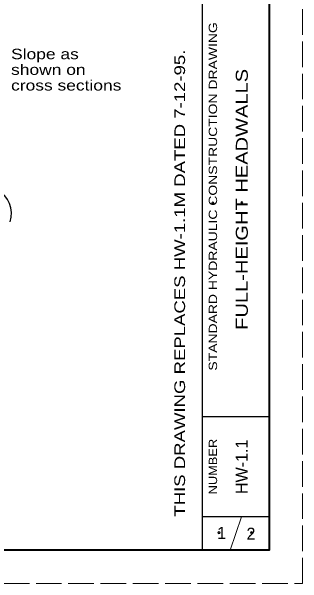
# Model space of a CAD drawing. Extents: x 1083.1 to 1117.1, y 697.4 to 743.4.
# Drawn here: x 1112.77 to 1117.13, y 721.35 to 729.93 of the extents above; entities that cross this region are included whole.
import ezdxf
from ezdxf.enums import TextEntityAlignment as Align

# ---------------------------------------------------------------- set-up
doc = ezdxf.new("R2010")
doc.units = 0
doc.header["$LTSCALE"] = 0.064
doc.header["$PDMODE"] = 32
doc.header["$PDSIZE"] = 0.032
doc.linetypes.add('LONG_DASHED', pattern=[7.5, 6, -1.5])
doc.layers.add('1', color=7, linetype='Continuous', lineweight=13)

msp = doc.modelspace()

# ---------------------------------------------------------------- linework, layer by layer
at = {"layer": '1', "lineweight": 25}
for p, q in [((1115.62642, 721.85408), (1115.62642, 742.85408)), ((1116.62642, 723.85408), (1115.62642, 723.85408)), ((1116.62642, 722.35408), (1115.62642, 722.35408))]:
    msp.add_line(p, q, dxfattribs=at)
at = {"layer": '1'}
msp.add_line((1116.04308, 721.85408), (1116.20975, 722.35408), dxfattribs=at)
at = {"layer": '1', "linetype": 'LONG_DASHED'}
msp.add_lwpolyline([(1083.12642, 721.35408), (1117.12642, 721.35408), (1117.12642, 743.35408), (1083.12642, 743.35408)], close=True, dxfattribs=at)
at = {"layer": '1', "lineweight": 25}
msp.add_lwpolyline([(1085.12642, 742.85408), (1116.62642, 742.85408), (1116.62642, 721.85408), (1085.12642, 721.85408)], close=True, dxfattribs=at)
at = {"layer": '1', "lineweight": 40}
msp.add_lwpolyline([(1085.12642, 742.85408), (1116.62642, 742.85408), (1116.62642, 721.85408), (1085.12642, 721.85408)], close=True, dxfattribs=at)
msp.add_lwpolyline([(1085.12642, 742.85408), (1116.62642, 742.85408), (1116.62642, 721.85408), (1085.12642, 721.85408)], close=True, dxfattribs=at)
at = {"layer": '1', "lineweight": 25}
msp.add_ellipse((1112.36624, 726.90056), major_axis=(0.40134, 0), ratio=0.999895, start_param=5.9747024, end_param=7.3677783, dxfattribs=at)
at = {"layer": '1'}
for p in [(1115.78383, 727.06008), (1116.21667, 727.06742), (1115.8745, 722.11783), (1116.36292, 722.11683)]:
    msp.add_point(p, dxfattribs=at)

# ---------------------------------------------------------------- texts
for s, height, width, p in [('STANDARD HYDRAULIC CONSTRUCTION DRAWING', 0.125, 1.25, (1115.84633, 727.15812)), ('THIS DRAWING REPLACES HW-1.1M DATED 7-12-95.', 0.16, 1.3, (1115.36683, 725.85787)), ('FULL-HEIGHT HEADWALLS', 0.18, 1.25, (1116.30683, 727.11425)), ('NUMBER', 0.125, 1.15, (1115.84642, 723.10817))]:
    msp.add_text(s, height=height, rotation=90, dxfattribs=dict(at, width=width)).set_placement(p, align=Align.CENTER)
at = {"layer": '1', "width": 1.25}
for s, p in [('Slope as', (1112.761, 729.21533)), ('shown on', (1112.761, 728.98067)), ('cross sections', (1112.761, 728.746))]:
    msp.add_text(s, height=0.156, dxfattribs=at).set_placement(p)
at = {"layer": '1'}
msp.add_text('HW-1.1', height=0.18, rotation=90, dxfattribs=at).set_placement((1116.3055, 723.10442), align=Align.CENTER)
for s, p in [('1', (1115.91427, 722.02417)), ('2', (1116.35371, 722.01158))]:
    msp.add_text(s, height=0.18, dxfattribs=at).set_placement(p, align=Align.CENTER)

doc.saveas('drawing.dxf')
